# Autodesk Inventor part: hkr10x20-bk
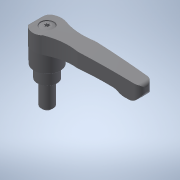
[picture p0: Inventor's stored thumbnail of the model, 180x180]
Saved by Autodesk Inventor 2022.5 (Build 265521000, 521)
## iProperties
Created: 2017-09
Part Number: hkr10x20-bk
Material: 一般
Document SubType Name: Modeling
Designer: imaocorp
Density: 1 g/cm^3
Appearance: 既定
Author: imaocorp
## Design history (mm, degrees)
node "hkr10x20-bk.x_t1"
node "hkr10x20-bk"
node "Base1"
